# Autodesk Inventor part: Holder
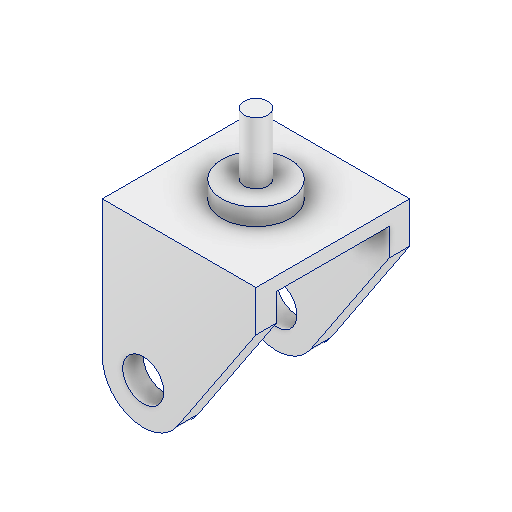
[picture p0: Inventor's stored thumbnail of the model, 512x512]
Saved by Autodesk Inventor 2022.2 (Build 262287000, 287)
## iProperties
Created: 2021-12
Part Number: Holder
Material: アルミニウム 6061
Document SubType Name: Modeling
Designer: taeku
Density: 2.7 g/cm^3
Appearance: アルミニウム - フラット
Author: taeku
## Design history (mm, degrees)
sketch "スケッチ1"
  geometry: L1 (9.996, -6.639)-(33, 28); L2 (-12, 0)-(-12, 40); L3 (-12, 40)-(33, 40); L4 (33, 40)-(33, 28); A1 r 12 centre (0, 0) between (-12, 0) and (9.996, -6.639); 1 further point
  constraints: 8 end point, 2 point on circle, 2 tangent, 2 vertical, 1 centre point, 1 coincident, 1 perpendicular
  dimensions: "d12" = 12 radius of A1; "d13" = 40 distance from line of L3 point (0, 0); "d25" = 45 distance of L2.end L3.end; "d26" = 12 distance of L3.end L1.end
extrude "押し出し1" new body sketch "スケッチ1" stored distance "d0" = 45; taper "d1" = 0 deg
sketch "スケッチ2"
  geometry: L1 (-45, 40)-(0, 40) reference; L2 (-22.5, 40)-(-22.5, -35.904); L3 (-45, -12)-(0, -12) reference; L4 (-6, -12)-(-6, 36); L5 (-6, 36)-(-39, 36); L6 (-39, 36)-(-39, -12); L7 (-6.5, 10.5)-(-6.5, -10.5) reference; L8 (0, 0)-(-45, 0) reference; L9 (0, 40)-(0, 0) reference; L10 (-45, 40)-(0, 40) reference; L11 (-45, 0)-(-45, 40) reference; 3 further points
  constraints: 8 end point, 2 perpendicular, 2 point on line, 2 vertical, 1 midpoint, 1 other
  dimensions: "d2" = 0.5 distance between parallel lines of L4 L7; "d14" = 36 distance between parallel lines of L5 L8 (computed from d13); "d27" = 6 distance between parallel lines of L4 L9 (derived); "d28" = 4 distance between parallel lines of L1 L5 (derived)
extrude "押し出し2" cut sketch "スケッチ2" extent not by distance; stored distance "d3" = 0; taper "d4" = 0 deg
sketch "スケッチ3"
  geometry: A1 r 12 centre (0, 0) between (-12, 0) and (9.996, -6.639) reference; 2 further points
  constraints: 1 coincident
hole "穴1" sketch "スケッチ3" at (0, 0) diameter "d5" = 12; stored, may be unused: countersink angle "d9" = 90 deg, drill point angle "d11" = 118 deg; dims "d6" = 6, "d7" = 4, "d8" = 2, "d10" = 8
sketch "スケッチ4"
  geometry: L1 (0, 39)-(0, 6) reference; L2 (0, 22.5)-(45, 22.5); L3 (45, 6)-(45, 39) reference; L4 (0, 45)-(45, 45) reference; L5 (22.5, 45)-(22.5, 0); L6 (45, 0)-(0, 0) reference; C1 r 10 at (22.5, 22.5); 1 further point
  constraints: 5 midpoint, 4 end point, 1 centre point
  dimensions: "d15" = 20 diameter of C1
extrude "押し出し3" join sketch "スケッチ4" distance "d16" = 5; taper "d17" = 0 deg
sketch "スケッチ5"
  geometry: C1 r 3.5 at (0, 0); 1 further point
  constraints: 1 centre point
  dimensions: "d18" = 7 diameter of C1
extrude "押し出し4" join sketch "スケッチ5" distance "d19" = 18; taper "d20" = 0 deg
fillet "フィレット1" dims "d21" = 0.5
chamfer "面取り1" distance "d22" = 0.5; stored, may be unused: second distance "d23" = 2, angle "d24" = 45 deg
node "ソリッド1"
node "参照1"
node "投影ループ1"
